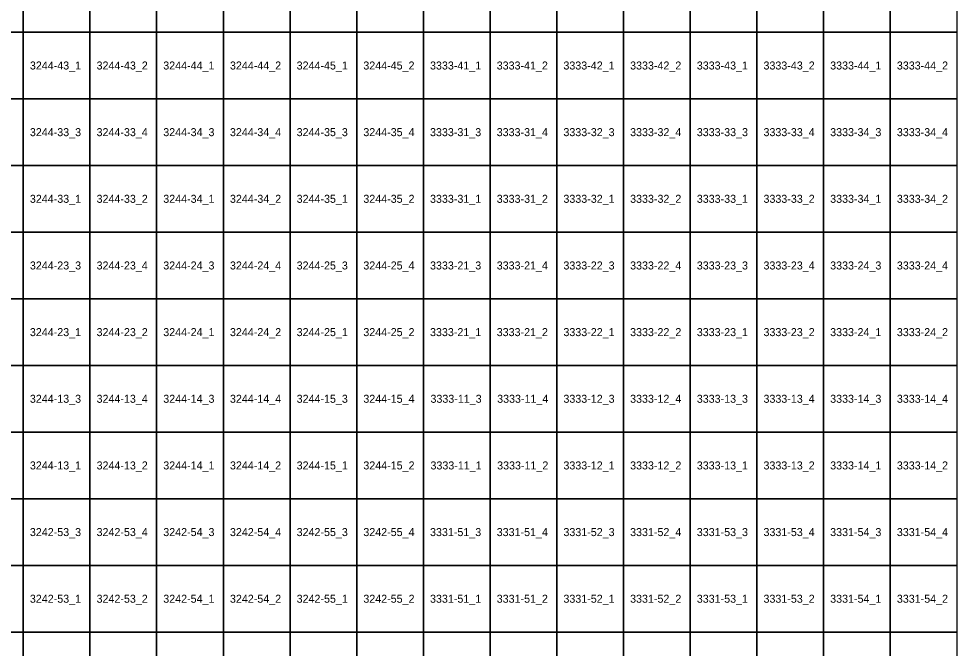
# Model space of a CAD drawing. Extents: x 312500 to 765000, y 172500 to 440000.
# Drawn here: x 484827 to 519827, y 269390 to 293007 of the extents above; entities that cross this region are included whole.
import ezdxf

# ---------------------------------------------------------------- set-up
doc = ezdxf.new("R2010")
doc.units = 0
doc.layers.add('Topo5_ramis_TKS2025', color=7, linetype='Continuous')
doc.layers.add('Topo5_ramis_TKS2025_Nr', color=7, linetype='Continuous')

msp = doc.modelspace()

# ---------------------------------------------------------------- linework, layer by layer
at = {"layer": 'Topo5_ramis_TKS2025'}
for points in [[(482500, 292500), (482500, 295000), (485000, 295000), (485000, 292500), (482500, 292500)], [(485000, 292500), (485000, 295000), (487500, 295000), (487500, 292500), (485000, 292500)], [(487500, 292500), (487500, 295000), (490000, 295000), (490000, 292500), (487500, 292500)], [(490000, 292500), (490000, 295000), (492500, 295000), (492500, 292500), (490000, 292500)], [(492500, 292500), (492500, 295000), (495000, 295000), (495000, 292500), (492500, 292500)], [(495000, 292500), (495000, 295000), (497500, 295000), (497500, 292500), (495000, 292500)], [(497500, 292500), (497500, 295000), (500000, 295000), (500000, 292500), (497500, 292500)], [(500000, 292500), (500000, 295000), (502500, 295000), (502500, 292500), (500000, 292500)], [(502500, 292500), (502500, 295000), (505000, 295000), (505000, 292500), (502500, 292500)], [(505000, 292500), (505000, 295000), (507500, 295000), (507500, 292500), (505000, 292500)], [(507500, 292500), (507500, 295000), (510000, 295000), (510000, 292500), (507500, 292500)], [(510000, 292500), (510000, 295000), (512500, 295000), (512500, 292500), (510000, 292500)], [(512500, 292500), (512500, 295000), (515000, 295000), (515000, 292500), (512500, 292500)], [(515000, 292500), (515000, 295000), (517500, 295000), (517500, 292500), (515000, 292500)], [(517500, 292500), (517500, 295000), (520000, 295000), (520000, 292500), (517500, 292500)], [(482500, 290000), (482500, 292500), (485000, 292500), (485000, 290000), (482500, 290000)], [(485000, 290000), (485000, 292500), (487500, 292500), (487500, 290000), (485000, 290000)], [(487500, 290000), (487500, 292500), (490000, 292500), (490000, 290000), (487500, 290000)], [(490000, 290000), (490000, 292500), (492500, 292500), (492500, 290000), (490000, 290000)], [(492500, 290000), (492500, 292500), (495000, 292500), (495000, 290000), (492500, 290000)], [(495000, 290000), (495000, 292500), (497500, 292500), (497500, 290000), (495000, 290000)], [(497500, 290000), (497500, 292500), (500000, 292500), (500000, 290000), (497500, 290000)], [(500000, 290000), (500000, 292500), (502500, 292500), (502500, 290000), (500000, 290000)], [(502500, 290000), (502500, 292500), (505000, 292500), (505000, 290000), (502500, 290000)], [(505000, 290000), (505000, 292500), (507500, 292500), (507500, 290000), (505000, 290000)], [(507500, 290000), (507500, 292500), (510000, 292500), (510000, 290000), (507500, 290000)], [(510000, 290000), (510000, 292500), (512500, 292500), (512500, 290000), (510000, 290000)], [(512500, 290000), (512500, 292500), (515000, 292500), (515000, 290000), (512500, 290000)], [(515000, 290000), (515000, 292500), (517500, 292500), (517500, 290000), (515000, 290000)], [(517500, 290000), (517500, 292500), (520000, 292500), (520000, 290000), (517500, 290000)], [(482500, 287500), (482500, 290000), (485000, 290000), (485000, 287500), (482500, 287500)], [(485000, 287500), (485000, 290000), (487500, 290000), (487500, 287500), (485000, 287500)], [(487500, 287500), (487500, 290000), (490000, 290000), (490000, 287500), (487500, 287500)], [(490000, 287500), (490000, 290000), (492500, 290000), (492500, 287500), (490000, 287500)], [(492500, 287500), (492500, 290000), (495000, 290000), (495000, 287500), (492500, 287500)], [(495000, 287500), (495000, 290000), (497500, 290000), (497500, 287500), (495000, 287500)], [(497500, 287500), (497500, 290000), (500000, 290000), (500000, 287500), (497500, 287500)], [(500000, 287500), (500000, 290000), (502500, 290000), (502500, 287500), (500000, 287500)], [(502500, 287500), (502500, 290000), (505000, 290000), (505000, 287500), (502500, 287500)], [(505000, 287500), (505000, 290000), (507500, 290000), (507500, 287500), (505000, 287500)], [(507500, 287500), (507500, 290000), (510000, 290000), (510000, 287500), (507500, 287500)], [(510000, 287500), (510000, 290000), (512500, 290000), (512500, 287500), (510000, 287500)], [(512500, 287500), (512500, 290000), (515000, 290000), (515000, 287500), (512500, 287500)], [(515000, 287500), (515000, 290000), (517500, 290000), (517500, 287500), (515000, 287500)], [(517500, 287500), (517500, 290000), (520000, 290000), (520000, 287500), (517500, 287500)], [(482500, 285000), (482500, 287500), (485000, 287500), (485000, 285000), (482500, 285000)], [(485000, 285000), (485000, 287500), (487500, 287500), (487500, 285000), (485000, 285000)], [(487500, 285000), (487500, 287500), (490000, 287500), (490000, 285000), (487500, 285000)], [(490000, 285000), (490000, 287500), (492500, 287500), (492500, 285000), (490000, 285000)], [(492500, 285000), (492500, 287500), (495000, 287500), (495000, 285000), (492500, 285000)], [(495000, 285000), (495000, 287500), (497500, 287500), (497500, 285000), (495000, 285000)], [(497500, 285000), (497500, 287500), (500000, 287500), (500000, 285000), (497500, 285000)], [(500000, 285000), (500000, 287500), (502500, 287500), (502500, 285000), (500000, 285000)], [(502500, 285000), (502500, 287500), (505000, 287500), (505000, 285000), (502500, 285000)], [(505000, 285000), (505000, 287500), (507500, 287500), (507500, 285000), (505000, 285000)], [(507500, 285000), (507500, 287500), (510000, 287500), (510000, 285000), (507500, 285000)], [(510000, 285000), (510000, 287500), (512500, 287500), (512500, 285000), (510000, 285000)], [(512500, 285000), (512500, 287500), (515000, 287500), (515000, 285000), (512500, 285000)], [(515000, 285000), (515000, 287500), (517500, 287500), (517500, 285000), (515000, 285000)], [(517500, 285000), (517500, 287500), (520000, 287500), (520000, 285000), (517500, 285000)], [(482500, 282500), (482500, 285000), (485000, 285000), (485000, 282500), (482500, 282500)], [(485000, 282500), (485000, 285000), (487500, 285000), (487500, 282500), (485000, 282500)], [(487500, 282500), (487500, 285000), (490000, 285000), (490000, 282500), (487500, 282500)], [(490000, 282500), (490000, 285000), (492500, 285000), (492500, 282500), (490000, 282500)], [(492500, 282500), (492500, 285000), (495000, 285000), (495000, 282500), (492500, 282500)], [(495000, 282500), (495000, 285000), (497500, 285000), (497500, 282500), (495000, 282500)], [(497500, 282500), (497500, 285000), (500000, 285000), (500000, 282500), (497500, 282500)], [(500000, 282500), (500000, 285000), (502500, 285000), (502500, 282500), (500000, 282500)], [(502500, 282500), (502500, 285000), (505000, 285000), (505000, 282500), (502500, 282500)], [(505000, 282500), (505000, 285000), (507500, 285000), (507500, 282500), (505000, 282500)], [(507500, 282500), (507500, 285000), (510000, 285000), (510000, 282500), (507500, 282500)], [(510000, 282500), (510000, 285000), (512500, 285000), (512500, 282500), (510000, 282500)], [(512500, 282500), (512500, 285000), (515000, 285000), (515000, 282500), (512500, 282500)], [(515000, 282500), (515000, 285000), (517500, 285000), (517500, 282500), (515000, 282500)], [(517500, 282500), (517500, 285000), (520000, 285000), (520000, 282500), (517500, 282500)], [(482500, 280000), (482500, 282500), (485000, 282500), (485000, 280000), (482500, 280000)], [(485000, 280000), (485000, 282500), (487500, 282500), (487500, 280000), (485000, 280000)], [(487500, 280000), (487500, 282500), (490000, 282500), (490000, 280000), (487500, 280000)], [(490000, 280000), (490000, 282500), (492500, 282500), (492500, 280000), (490000, 280000)], [(492500, 280000), (492500, 282500), (495000, 282500), (495000, 280000), (492500, 280000)], [(495000, 280000), (495000, 282500), (497500, 282500), (497500, 280000), (495000, 280000)], [(497500, 280000), (497500, 282500), (500000, 282500), (500000, 280000), (497500, 280000)], [(500000, 280000), (500000, 282500), (502500, 282500), (502500, 280000), (500000, 280000)], [(502500, 280000), (502500, 282500), (505000, 282500), (505000, 280000), (502500, 280000)], [(505000, 280000), (505000, 282500), (507500, 282500), (507500, 280000), (505000, 280000)], [(507500, 280000), (507500, 282500), (510000, 282500), (510000, 280000), (507500, 280000)], [(510000, 280000), (510000, 282500), (512500, 282500), (512500, 280000), (510000, 280000)], [(512500, 280000), (512500, 282500), (515000, 282500), (515000, 280000), (512500, 280000)], [(515000, 280000), (515000, 282500), (517500, 282500), (517500, 280000), (515000, 280000)], [(517500, 280000), (517500, 282500), (520000, 282500), (520000, 280000), (517500, 280000)], [(482500, 277500), (482500, 280000), (485000, 280000), (485000, 277500), (482500, 277500)], [(485000, 277500), (485000, 280000), (487500, 280000), (487500, 277500), (485000, 277500)], [(487500, 277500), (487500, 280000), (490000, 280000), (490000, 277500), (487500, 277500)], [(490000, 277500), (490000, 280000), (492500, 280000), (492500, 277500), (490000, 277500)], [(492500, 277500), (492500, 280000), (495000, 280000), (495000, 277500), (492500, 277500)], [(495000, 277500), (495000, 280000), (497500, 280000), (497500, 277500), (495000, 277500)], [(497500, 277500), (497500, 280000), (500000, 280000), (500000, 277500), (497500, 277500)], [(500000, 277500), (500000, 280000), (502500, 280000), (502500, 277500), (500000, 277500)], [(502500, 277500), (502500, 280000), (505000, 280000), (505000, 277500), (502500, 277500)], [(505000, 277500), (505000, 280000), (507500, 280000), (507500, 277500), (505000, 277500)], [(507500, 277500), (507500, 280000), (510000, 280000), (510000, 277500), (507500, 277500)], [(510000, 277500), (510000, 280000), (512500, 280000), (512500, 277500), (510000, 277500)], [(512500, 277500), (512500, 280000), (515000, 280000), (515000, 277500), (512500, 277500)], [(515000, 277500), (515000, 280000), (517500, 280000), (517500, 277500), (515000, 277500)], [(517500, 277500), (517500, 280000), (520000, 280000), (520000, 277500), (517500, 277500)], [(482500, 275000), (482500, 277500), (485000, 277500), (485000, 275000), (482500, 275000)], [(485000, 275000), (485000, 277500), (487500, 277500), (487500, 275000), (485000, 275000)], [(487500, 275000), (487500, 277500), (490000, 277500), (490000, 275000), (487500, 275000)], [(490000, 275000), (490000, 277500), (492500, 277500), (492500, 275000), (490000, 275000)], [(492500, 275000), (492500, 277500), (495000, 277500), (495000, 275000), (492500, 275000)], [(495000, 275000), (495000, 277500), (497500, 277500), (497500, 275000), (495000, 275000)], [(497500, 275000), (497500, 277500), (500000, 277500), (500000, 275000), (497500, 275000)], [(500000, 275000), (500000, 277500), (502500, 277500), (502500, 275000), (500000, 275000)], [(502500, 275000), (502500, 277500), (505000, 277500), (505000, 275000), (502500, 275000)], [(505000, 275000), (505000, 277500), (507500, 277500), (507500, 275000), (505000, 275000)], [(507500, 275000), (507500, 277500), (510000, 277500), (510000, 275000), (507500, 275000)], [(510000, 275000), (510000, 277500), (512500, 277500), (512500, 275000), (510000, 275000)], [(512500, 275000), (512500, 277500), (515000, 277500), (515000, 275000), (512500, 275000)], [(515000, 275000), (515000, 277500), (517500, 277500), (517500, 275000), (515000, 275000)], [(517500, 275000), (517500, 277500), (520000, 277500), (520000, 275000), (517500, 275000)], [(482500, 272500), (482500, 275000), (485000, 275000), (485000, 272500), (482500, 272500)], [(485000, 272500), (485000, 275000), (487500, 275000), (487500, 272500), (485000, 272500)], [(487500, 272500), (487500, 275000), (490000, 275000), (490000, 272500), (487500, 272500)], [(490000, 272500), (490000, 275000), (492500, 275000), (492500, 272500), (490000, 272500)], [(492500, 272500), (492500, 275000), (495000, 275000), (495000, 272500), (492500, 272500)], [(495000, 272500), (495000, 275000), (497500, 275000), (497500, 272500), (495000, 272500)], [(497500, 272500), (497500, 275000), (500000, 275000), (500000, 272500), (497500, 272500)], [(500000, 272500), (500000, 275000), (502500, 275000), (502500, 272500), (500000, 272500)], [(502500, 272500), (502500, 275000), (505000, 275000), (505000, 272500), (502500, 272500)], [(505000, 272500), (505000, 275000), (507500, 275000), (507500, 272500), (505000, 272500)], [(507500, 272500), (507500, 275000), (510000, 275000), (510000, 272500), (507500, 272500)], [(510000, 272500), (510000, 275000), (512500, 275000), (512500, 272500), (510000, 272500)], [(512500, 272500), (512500, 275000), (515000, 275000), (515000, 272500), (512500, 272500)], [(515000, 272500), (515000, 275000), (517500, 275000), (517500, 272500), (515000, 272500)], [(517500, 272500), (517500, 275000), (520000, 275000), (520000, 272500), (517500, 272500)], [(482500, 270000), (482500, 272500), (485000, 272500), (485000, 270000), (482500, 270000)], [(485000, 270000), (485000, 272500), (487500, 272500), (487500, 270000), (485000, 270000)], [(487500, 270000), (487500, 272500), (490000, 272500), (490000, 270000), (487500, 270000)], [(490000, 270000), (490000, 272500), (492500, 272500), (492500, 270000), (490000, 270000)], [(492500, 270000), (492500, 272500), (495000, 272500), (495000, 270000), (492500, 270000)], [(495000, 270000), (495000, 272500), (497500, 272500), (497500, 270000), (495000, 270000)], [(497500, 270000), (497500, 272500), (500000, 272500), (500000, 270000), (497500, 270000)], [(500000, 270000), (500000, 272500), (502500, 272500), (502500, 270000), (500000, 270000)], [(502500, 270000), (502500, 272500), (505000, 272500), (505000, 270000), (502500, 270000)], [(505000, 270000), (505000, 272500), (507500, 272500), (507500, 270000), (505000, 270000)], [(507500, 270000), (507500, 272500), (510000, 272500), (510000, 270000), (507500, 270000)], [(510000, 270000), (510000, 272500), (512500, 272500), (512500, 270000), (510000, 270000)], [(512500, 270000), (512500, 272500), (515000, 272500), (515000, 270000), (512500, 270000)], [(515000, 270000), (515000, 272500), (517500, 272500), (517500, 270000), (515000, 270000)], [(517500, 270000), (517500, 272500), (520000, 272500), (520000, 270000), (517500, 270000)], [(482500, 267500), (482500, 270000), (485000, 270000), (485000, 267500), (482500, 267500)], [(485000, 267500), (485000, 270000), (487500, 270000), (487500, 267500), (485000, 267500)], [(487500, 267500), (487500, 270000), (490000, 270000), (490000, 267500), (487500, 267500)], [(490000, 267500), (490000, 270000), (492500, 270000), (492500, 267500), (490000, 267500)], [(492500, 267500), (492500, 270000), (495000, 270000), (495000, 267500), (492500, 267500)], [(495000, 267500), (495000, 270000), (497500, 270000), (497500, 267500), (495000, 267500)], [(497500, 267500), (497500, 270000), (500000, 270000), (500000, 267500), (497500, 267500)], [(500000, 267500), (500000, 270000), (502500, 270000), (502500, 267500), (500000, 267500)], [(502500, 267500), (502500, 270000), (505000, 270000), (505000, 267500), (502500, 267500)], [(505000, 267500), (505000, 270000), (507500, 270000), (507500, 267500), (505000, 267500)], [(507500, 267500), (507500, 270000), (510000, 270000), (510000, 267500), (507500, 267500)], [(510000, 267500), (510000, 270000), (512500, 270000), (512500, 267500), (510000, 267500)], [(512500, 267500), (512500, 270000), (515000, 270000), (515000, 267500), (512500, 267500)], [(515000, 267500), (515000, 270000), (517500, 270000), (517500, 267500), (515000, 267500)], [(517500, 267500), (517500, 270000), (520000, 270000), (520000, 267500), (517500, 267500)]]:
    msp.add_lwpolyline(points, dxfattribs=at)

# ---------------------------------------------------------------- texts
at = {"layer": 'Topo5_ramis_TKS2025_Nr'}
for s, p in [('3244-43_1', (485248, 291100)), ('3244-43_2', (487748, 291100)), ('3244-44_1', (490248, 291100)), ('3244-44_2', (492748, 291100)), ('3244-45_1', (495248, 291100)), ('3244-45_2', (497748, 291100)), ('3333-41_1', (500248, 291100)), ('3333-41_2', (502748, 291100)), ('3333-42_1', (505248, 291100)), ('3333-42_2', (507748, 291100)), ('3333-43_1', (510248, 291100)), ('3333-43_2', (512748, 291100)), ('3333-44_1', (515248, 291100)), ('3333-44_2', (517748, 291100)), ('3244-33_3', (485248, 288600)), ('3244-33_4', (487748, 288600)), ('3244-34_3', (490248, 288600)), ('3244-34_4', (492748, 288600)), ('3244-35_3', (495248, 288600)), ('3244-35_4', (497748, 288600)), ('3333-31_3', (500248, 288600)), ('3333-31_4', (502748, 288600)), ('3333-32_3', (505248, 288600)), ('3333-32_4', (507748, 288600)), ('3333-33_3', (510248, 288600)), ('3333-33_4', (512748, 288600)), ('3333-34_3', (515248, 288600)), ('3333-34_4', (517748, 288600)), ('3244-33_1', (485248, 286100)), ('3244-33_2', (487748, 286100)), ('3244-34_1', (490248, 286100)), ('3244-34_2', (492748, 286100)), ('3244-35_1', (495248, 286100)), ('3244-35_2', (497748, 286100)), ('3333-31_1', (500248, 286100)), ('3333-31_2', (502748, 286100)), ('3333-32_1', (505248, 286100)), ('3333-32_2', (507748, 286100)), ('3333-33_1', (510248, 286100)), ('3333-33_2', (512748, 286100)), ('3333-34_1', (515248, 286100)), ('3333-34_2', (517748, 286100)), ('3244-23_3', (485248, 283600)), ('3244-23_4', (487748, 283600)), ('3244-24_3', (490248, 283600)), ('3244-24_4', (492748, 283600)), ('3244-25_3', (495248, 283600)), ('3244-25_4', (497748, 283600)), ('3333-21_3', (500248, 283600)), ('3333-21_4', (502748, 283600)), ('3333-22_3', (505248, 283600)), ('3333-22_4', (507748, 283600)), ('3333-23_3', (510248, 283600)), ('3333-23_4', (512748, 283600)), ('3333-24_3', (515248, 283600)), ('3333-24_4', (517748, 283600)), ('3244-23_1', (485248, 281100)), ('3244-23_2', (487748, 281100)), ('3244-24_1', (490248, 281100)), ('3244-24_2', (492748, 281100)), ('3244-25_1', (495248, 281100)), ('3244-25_2', (497748, 281100)), ('3333-21_1', (500248, 281100)), ('3333-21_2', (502748, 281100)), ('3333-22_1', (505248, 281100)), ('3333-22_2', (507748, 281100)), ('3333-23_1', (510248, 281100)), ('3333-23_2', (512748, 281100)), ('3333-24_1', (515248, 281100)), ('3333-24_2', (517748, 281100)), ('3244-13_3', (485248, 278600)), ('3244-13_4', (487748, 278600)), ('3244-14_3', (490248, 278600)), ('3244-14_4', (492748, 278600)), ('3244-15_3', (495248, 278600)), ('3244-15_4', (497748, 278600)), ('3333-11_3', (500264, 278600)), ('3333-11_4', (502764, 278600)), ('3333-12_3', (505248, 278600)), ('3333-12_4', (507748, 278600)), ('3333-13_3', (510248, 278600)), ('3333-13_4', (512748, 278600)), ('3333-14_3', (515248, 278600)), ('3333-14_4', (517748, 278600)), ('3244-13_1', (485248, 276100)), ('3244-13_2', (487748, 276100)), ('3244-14_1', (490248, 276100)), ('3244-14_2', (492748, 276100)), ('3244-15_1', (495248, 276100)), ('3244-15_2', (497748, 276100)), ('3333-11_1', (500264, 276100)), ('3333-11_2', (502764, 276100)), ('3333-12_1', (505248, 276100)), ('3333-12_2', (507748, 276100)), ('3333-13_1', (510248, 276100)), ('3333-13_2', (512748, 276100)), ('3333-14_1', (515248, 276100)), ('3333-14_2', (517748, 276100)), ('3242-53_3', (485248, 273600)), ('3242-53_4', (487748, 273600)), ('3242-54_3', (490248, 273600)), ('3242-54_4', (492748, 273600)), ('3242-55_3', (495248, 273600)), ('3242-55_4', (497748, 273600)), ('3331-51_3', (500248, 273600)), ('3331-51_4', (502748, 273600)), ('3331-52_3', (505248, 273600)), ('3331-52_4', (507748, 273600)), ('3331-53_3', (510248, 273600)), ('3331-53_4', (512748, 273600)), ('3331-54_3', (515248, 273600)), ('3331-54_4', (517748, 273600)), ('3242-53_1', (485248, 271100)), ('3242-53_2', (487748, 271100)), ('3242-54_1', (490248, 271100)), ('3242-54_2', (492748, 271100)), ('3242-55_1', (495248, 271100)), ('3242-55_2', (497748, 271100)), ('3331-51_1', (500248, 271100)), ('3331-51_2', (502748, 271100)), ('3331-52_1', (505248, 271100)), ('3331-52_2', (507748, 271100)), ('3331-53_1', (510248, 271100)), ('3331-53_2', (512748, 271100)), ('3331-54_1', (515248, 271100)), ('3331-54_2', (517748, 271100))]:
    msp.add_text(s, height=300, dxfattribs=at).set_placement(p)

doc.saveas('drawing.dxf')
